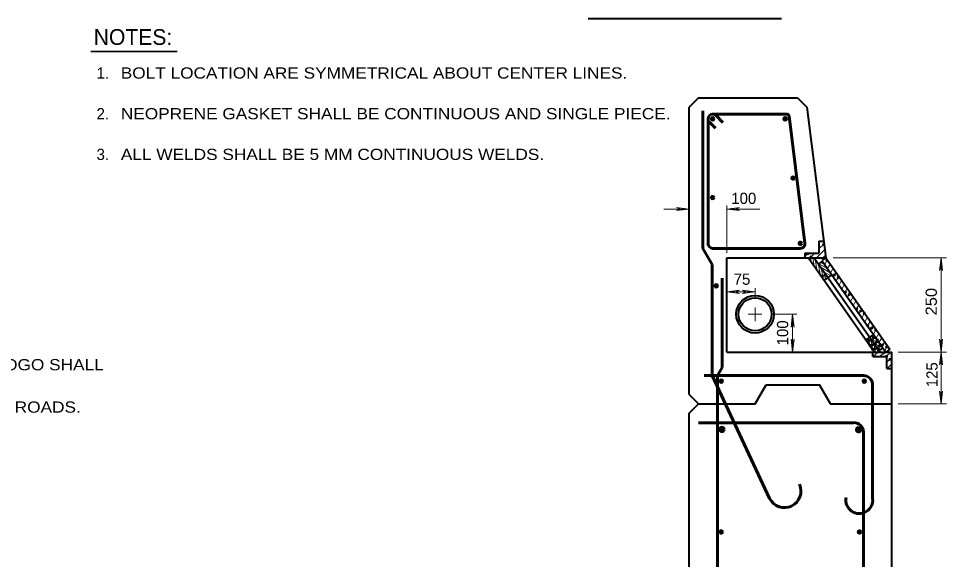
# Model space of a CAD drawing. Extents: x 312583 to 312854, y 144419 to 144597.
# Drawn here: x 312713.6 to 312776.5, y 144507.6 to 144544.3 of the extents above; entities that cross this region are included whole.
import ezdxf
from ezdxf.enums import TextEntityAlignment as Align

# ---------------------------------------------------------------- set-up
doc = ezdxf.new("R2010")
doc.units = 0
doc.header["$LTSCALE"] = 0.3
doc.header["$PDMODE"] = 32
doc.header["$PDSIZE"] = 0.15
doc.layers.add('1', color=7, linetype='Continuous', lineweight=13)

msp = doc.modelspace()

# ---------------------------------------------------------------- linework, layer by layer
at = {"layer": '1', "lineweight": 40}
for p, q in [((312752.2333, 144544.2744), (312765.3439, 144544.2744)), ((312759.7265, 144538.9071), (312759.0902, 144538.2708)), ((312759.7265, 144538.9071), (312766.4348, 144538.9071)), ((312759.0902, 144518.7821), (312759.0902, 144538.2708)), ((312767.8915, 144529.1704), (312767.8915, 144528.3654)), ((312767.8915, 144529.1704), (312768.2135, 144529.1704)), ((312766.9332, 144528.3654), (312767.8915, 144528.3654)), ((312766.9332, 144528.3654), (312766.9332, 144528.0511)), ((312761.6432, 144528.0511), (312768.3515, 144528.0511)), ((312761.6432, 144521.6571), (312761.6432, 144528.0511)), ((312767.1862, 144528.0511), (312771.6558, 144521.6571)), ((312767.5772, 144528.0511), (312772.0468, 144521.6571)), ((312768.1292, 144527.8134), (312767.8685, 144527.6294)), ((312768.3515, 144528.0511), (312768.0908, 144527.8671)), ((312768.0908, 144527.8671), (312772.4378, 144521.6571)), ((312768.3515, 144528.0511), (312772.6985, 144521.8411)), ((312768.7655, 144526.9011), (312768.2442, 144526.5331)), ((312771.6022, 144522.8531), (312771.0808, 144522.4851)), ((312772.2462, 144521.9331), (312771.9855, 144521.7568)), ((312761.6432, 144521.6571), (312772.8288, 144521.6571)), ((312771.5485, 144521.3428), (312771.5485, 144521.6571)), ((312771.5485, 144521.3428), (312772.5068, 144521.3428)), ((312772.6985, 144521.8411), (312772.4378, 144521.6571)), ((312772.5068, 144520.5454), (312772.5068, 144521.3428)), ((312772.8288, 144491.9488), (312772.8288, 144521.6571)), ((312772.5068, 144520.5454), (312772.8288, 144520.5454)), ((312763.5598, 144518.1458), (312764.3035, 144519.4261)), ((312764.3035, 144519.4261), (312767.9375, 144519.4261)), ((312768.6735, 144518.1458), (312767.9375, 144519.4261)), ((312759.0902, 144518.7821), (312759.7265, 144518.1458)), ((312759.0902, 144517.5094), (312759.7265, 144518.1458)), ((312759.7265, 144518.1458), (312763.5598, 144518.1458)), ((312768.6428, 144518.1458), (312772.8288, 144518.1458)), ((312759.0902, 144491.9488), (312759.0902, 144517.5094))]:
    msp.add_line(p, q, dxfattribs=at)
at = {"layer": '1', "lineweight": 35}
msp.add_line((312724.3562, 144542.0512), (312718.5131, 144542.0512), dxfattribs=at)
at = {"layer": '1', "lineweight": 60}
for p, q in [((312760.0178, 144528.6874), (312760.0178, 144538.0101)), ((312760.6848, 144537.7954), (312765.7065, 144537.7954)), ((312760.8918, 144537.7188), (312761.3748, 144537.2358)), ((312765.8675, 144537.6498), (312766.9408, 144529.0478)), ((312760.3705, 144529.0094), (312760.3705, 144537.4734)), ((312760.4472, 144537.2664), (312760.8688, 144536.8371)), ((312760.0178, 144528.6874), (312760.6542, 144527.5834)), ((312760.6848, 144528.6874), (312766.6265, 144528.6874)), ((312760.6542, 144520.0624), (312760.6542, 144527.5834)), ((312761.3288, 144520.6144), (312761.3288, 144526.6634)), ((312761.0068, 144520.0624), (312761.3288, 144520.6144)), ((312760.1022, 144520.0624), (312770.8968, 144520.0624)), ((312760.6542, 144520.0624), (312764.5488, 144511.7288)), ((312761.0068, 144491.9488), (312761.0068, 144520.0624)), ((312771.5332, 144511.7288), (312771.5332, 144519.4261)), ((312759.7265, 144516.8654), (312770.2682, 144516.8654)), ((312770.9122, 144491.9488), (312770.9122, 144516.2291))]:
    msp.add_line(p, q, dxfattribs=at)
at = {"layer": '1'}
for p, q in [((312757.3652, 144531.3554), (312759.0902, 144531.3554)), ((312758.2238, 144531.4628), (312758.4998, 144531.3554)), ((312759.0902, 144531.3554), (312758.2238, 144531.4628)), ((312758.2238, 144531.2481), (312758.4998, 144531.3554)), ((312759.0902, 144531.3554), (312758.2238, 144531.2481)), ((312761.6432, 144528.3961), (312761.6432, 144531.5931)), ((312761.6432, 144531.3554), (312762.5095, 144531.4628)), ((312761.6432, 144531.3554), (312763.8742, 144531.3554)), ((312761.6432, 144531.3554), (312762.5095, 144531.2481)), ((312762.5095, 144531.4628), (312762.2335, 144531.3554)), ((312762.5095, 144531.2481), (312762.2335, 144531.3554)), ((312767.8915, 144529.0861), (312767.9682, 144529.1704)), ((312767.8915, 144528.6568), (312768.2365, 144528.9941)), ((312766.9332, 144528.1278), (312767.1708, 144528.3654)), ((312767.2858, 144528.0511), (312767.6078, 144528.3654)), ((312767.7228, 144528.0511), (312768.2825, 144528.6108)), ((312768.1522, 144528.0511), (312768.3285, 144528.2274)), ((312767.3625, 144527.7981), (312767.3165, 144528.0511)), ((312767.5695, 144527.5068), (312767.4698, 144528.0511)), ((312767.7535, 144527.2308), (312767.6308, 144527.9744)), ((312767.9682, 144526.9394), (312767.8378, 144527.6754)), ((312768.4895, 144527.2998), (312767.8915, 144527.6448)), ((312768.2748, 144527.5988), (312768.0295, 144527.7444)), ((312768.2825, 144527.5911), (312768.4588, 144527.8978)), ((312768.4818, 144527.3151), (312768.6582, 144527.6218)), ((312768.8498, 144528.0511), (312776.5395, 144528.0511)), ((312776.1715, 144528.0511), (312776.0642, 144527.1848)), ((312776.1715, 144528.0511), (312776.2788, 144527.1848)), ((312768.6965, 144527.0084), (312768.0448, 144527.3841)), ((312768.1752, 144526.6404), (312768.0448, 144527.3841)), ((312768.6812, 144526.8398), (312768.2518, 144527.0851)), ((312768.3362, 144526.5944), (312768.2518, 144527.0851)), ((312768.6735, 144527.0391), (312768.8498, 144527.3381)), ((312768.8652, 144526.7554), (312769.0415, 144527.0621)), ((312776.0642, 144527.1848), (312776.1715, 144527.4608)), ((312776.2788, 144527.1848), (312776.1715, 144527.4608)), ((312768.4742, 144526.6941), (312768.4588, 144526.7784)), ((312768.5432, 144526.7401), (312768.4665, 144526.7861)), ((312769.0568, 144526.4794), (312769.2332, 144526.7861)), ((312769.2562, 144526.2034), (312769.4325, 144526.5101)), ((312761.6432, 144525.7358), (312762.5095, 144525.8431)), ((312761.6432, 144525.7358), (312763.5598, 144525.7358)), ((312761.6432, 144525.7358), (312762.5095, 144525.6284)), ((312762.5095, 144525.8431), (312762.2335, 144525.7358)), ((312762.5095, 144525.6284), (312762.2335, 144525.7358)), ((312762.6935, 144525.8431), (312762.9695, 144525.7358)), ((312763.5598, 144525.7358), (312762.6935, 144525.8431)), ((312762.6935, 144525.6284), (312762.9695, 144525.7358)), ((312763.5598, 144525.7358), (312762.6935, 144525.6284)), ((312763.5598, 144525.3141), (312763.5598, 144525.9888)), ((312769.4478, 144525.9274), (312769.6242, 144526.2341)), ((312769.6395, 144525.6514), (312769.8158, 144525.9581)), ((312769.8388, 144525.3754), (312770.0152, 144525.6821)), ((312770.0305, 144525.0918), (312770.2068, 144525.3984)), ((312770.2222, 144524.8158), (312770.3985, 144525.1224)), ((312763.5598, 144524.2178), (312763.5598, 144524.6778)), ((312770.4215, 144524.5398), (312770.5978, 144524.8464)), ((312770.6132, 144524.2638), (312770.7895, 144524.5704)), ((312763.5598, 144524.2178), (312763.0998, 144524.2178)), ((312763.5598, 144524.2178), (312764.0198, 144524.2178)), ((312763.5598, 144524.2178), (312763.5598, 144523.7578)), ((312764.7482, 144524.2178), (312766.3888, 144524.2178)), ((312766.1052, 144524.2178), (312765.9978, 144523.3514)), ((312766.1052, 144521.6571), (312766.1052, 144524.2178)), ((312766.1052, 144524.2178), (312766.2125, 144523.3514)), ((312770.8048, 144523.9878), (312770.9812, 144524.2944)), ((312771.0042, 144523.7118), (312771.1805, 144524.0184)), ((312765.9978, 144523.3514), (312766.1052, 144523.6274)), ((312766.2125, 144523.3514), (312766.1052, 144523.6274)), ((312771.1958, 144523.4358), (312771.3722, 144523.7348)), ((312771.3875, 144523.1521), (312771.5638, 144523.4588)), ((312771.5868, 144522.8761), (312771.7632, 144523.1828)), ((312765.9978, 144522.5234), (312766.1052, 144522.2474)), ((312766.1052, 144521.6571), (312765.9978, 144522.5234)), ((312766.2125, 144522.5234), (312766.1052, 144522.2474)), ((312766.1052, 144521.6571), (312766.2125, 144522.5234)), ((312771.1345, 144522.4084), (312771.1192, 144522.5081)), ((312771.3415, 144522.1171), (312771.2572, 144522.6078)), ((312772.0698, 144522.1861), (312771.4182, 144522.5618)), ((312771.5485, 144521.8181), (312771.4182, 144522.5618)), ((312771.8628, 144522.4774), (312771.4258, 144522.7304)), ((312771.6558, 144522.7764), (312771.5715, 144522.8224)), ((312771.7785, 144522.6001), (312771.9548, 144522.9068)), ((312771.9702, 144522.3241), (312772.1465, 144522.6308)), ((312776.0642, 144522.5234), (312776.1715, 144522.2474)), ((312776.1715, 144521.6571), (312776.0642, 144522.5234)), ((312776.2788, 144522.5234), (312776.1715, 144522.2474)), ((312776.1715, 144521.6571), (312776.2788, 144522.5234)), ((312772.2155, 144521.9178), (312771.6252, 144522.2628)), ((312771.7325, 144521.6571), (312771.6252, 144522.2628)), ((312771.8858, 144521.6571), (312771.8398, 144521.9484)), ((312772.0775, 144521.8258), (312771.8475, 144521.9561)), ((312772.1312, 144522.0941), (312772.2308, 144521.9254)), ((312772.1618, 144522.0481), (312772.3458, 144522.3548)), ((312772.3612, 144521.7721), (312772.5375, 144522.0788)), ((312771.5792, 144521.3428), (312771.9012, 144521.6571)), ((312771.6098, 144521.7261), (312771.6712, 144521.6571)), ((312772.0162, 144521.3428), (312772.3382, 144521.6571)), ((312772.4455, 144521.3428), (312772.7675, 144521.6571)), ((312772.5068, 144520.9671), (312772.8288, 144521.2814)), ((312773.2658, 144521.6571), (312776.5395, 144521.6571)), ((312776.1715, 144521.6571), (312776.0642, 144520.7908)), ((312776.1715, 144521.6571), (312776.2788, 144520.7908)), ((312772.5145, 144520.5454), (312772.8288, 144520.8521)), ((312776.0642, 144520.7908), (312776.1715, 144521.0668)), ((312776.2788, 144520.7908), (312776.1715, 144521.0668)), ((312776.0642, 144519.0121), (312776.1715, 144518.7361)), ((312776.1715, 144518.1458), (312776.0642, 144519.0121)), ((312776.2788, 144519.0121), (312776.1715, 144518.7361)), ((312776.1715, 144518.1458), (312776.2788, 144519.0121)), ((312773.2658, 144518.1458), (312776.5395, 144518.1458))]:
    msp.add_line(p, q, dxfattribs=at)
at = {"layer": '1', "lineweight": 40}
msp.add_lwpolyline([(312766.4348, 144538.9071), (312767.0788, 144538.2708), (312768.3515, 144528.0511)], dxfattribs=at)
at = {"layer": '1'}
msp.add_lwpolyline([(312776.1715, 144518.1458), (312776.1715, 144521.6571), (312776.1715, 144528.0511)], dxfattribs=at)
at = {"layer": '1', "lineweight": 60}
for centre, radius in [((312760.6867, 144537.4734), 0.085), ((312760.6867, 144537.4734), 0.051), ((312760.6867, 144537.4734), 0.0135), ((312765.6036, 144537.4734), 0.085), ((312765.6036, 144537.4734), 0.051), ((312765.6036, 144537.4734), 0.0135), ((312766.1326, 144533.4535), 0.085), ((312766.1326, 144533.4535), 0.051), ((312766.1326, 144533.4535), 0.0135), ((312760.681, 144532.1342), 0.085), ((312760.681, 144532.1342), 0.051), ((312760.681, 144532.1342), 0.0135), ((312766.6265, 144529.0292), 0.085), ((312766.6265, 144529.0292), 0.051), ((312766.6265, 144529.0292), 0.0135), ((312760.9276, 144526.144), 0.085), ((312760.9276, 144526.144), 0.051), ((312760.9276, 144526.144), 0.0135), ((312761.2707, 144519.6791), 0.085), ((312761.2707, 144519.6791), 0.051), ((312761.2707, 144519.6791), 0.0135), ((312770.9639, 144519.6791), 0.085), ((312770.9639, 144519.6791), 0.051), ((312770.9639, 144519.6791), 0.0135), ((312761.3111, 144516.4039), 0.1469), ((312761.3111, 144516.4039), 0.0881), ((312761.3111, 144516.4039), 0.0234), ((312770.5845, 144516.3909), 0.1469), ((312770.5845, 144516.3909), 0.0881), ((312770.5845, 144516.3909), 0.0234), ((312761.2707, 144509.4569), 0.085), ((312761.2707, 144509.4569), 0.051), ((312761.2707, 144509.4569), 0.0135), ((312770.6445, 144509.4569), 0.085), ((312770.6445, 144509.4569), 0.051), ((312770.6445, 144509.4569), 0.0135)]:
    msp.add_circle(centre, radius, dxfattribs=at)
at = {"layer": '1', "lineweight": 40}
for radius in [1.2778, 1.1181]:
    msp.add_circle((312763.5617, 144524.2165), radius, dxfattribs=at)
at = {"layer": '1', "lineweight": 60}
for centre, radius, start, end in [((312760.6867, 144537.4734), 0.3194, 50.2677, 221.03534), ((312765.7065, 144537.6332), 0.1597, 7.12502, 90), ((312760.6867, 144529.0082), 0.3194, 180, 270), ((312766.6237, 144529.0082), 0.3194, 270, 7.12548), ((312770.8956, 144519.4248), 0.6389, 0, 90), ((312770.2701, 144516.2304), 0.6389, 0, 90), ((312765.5525, 144512.2284), 1.122, 206.55046, 23.98617), ((312770.6279, 144511.6157), 0.9134, 169.41749, 6.9908)]:
    msp.add_arc(centre, radius, start, end, dxfattribs=at)
at = {"layer": '1'}
for p in [(312768.2058, 144528.9711), (312767.0022, 144528.3348), (312767.1248, 144528.3194), (312767.3395, 144528.1048), (312768.4435, 144527.8671), (312768.1445, 144526.8168), (312768.2902, 144526.8474), (312768.9342, 144526.8781), (312769.2025, 144526.7248), (312769.6932, 144525.7281), (312769.9538, 144525.5748), (312770.4445, 144524.5858), (312770.7128, 144524.4324), (312770.9735, 144524.2791), (312771.2035, 144523.4434), (312771.4642, 144523.2901), (312771.7325, 144523.1368), (312771.2878, 144522.4238), (312771.4412, 144522.4468), (312771.5178, 144522.5004), (312771.5945, 144522.6384), (312771.8552, 144522.4851), (312771.3415, 144522.1171), (312771.4948, 144522.1478), (312771.5408, 144521.8411), (312771.6405, 144522.1708), (312771.6405, 144522.1631), (312771.6942, 144521.8718), (312771.7018, 144522.2168), (312771.7095, 144522.2091), (312771.7785, 144522.3471), (312771.8475, 144521.8948), (312771.8935, 144521.9331), (312771.9702, 144522.0634), (312772.0468, 144522.1938), (312772.2232, 144522.1478), (312772.4915, 144521.9944), (312771.6175, 144521.3734), (312772.2692, 144521.5958), (312772.4838, 144521.3734), (312772.6985, 144521.1588)]:
    msp.add_point(p, dxfattribs=at)

# ---------------------------------------------------------------- texts
msp.add_text('NOTES:', height=1.07, dxfattribs=at).set_placement((312721.3684, 144542.4879), align=Align.CENTER)
for s, p in [('1. ', (312718.8976, 144540.2025)), ('2.', (312718.8976, 144537.4425)), ('3.', (312718.8976, 144534.6825)), ('100', (312761.9441, 144531.7024)), ('75', (312762.1086, 144526.2169))]:
    msp.add_text(s, height=0.76, dxfattribs=at).set_placement(p)
at = {"layer": '1', "width": 1.15}
for s, p in [('BOLT LOCATION ARE SYMMETRICAL ABOUT CENTER LINES.', (312720.5382, 144540.2025)), ('NEOPRENE GASKET SHALL BE CONTINUOUS AND SINGLE PIECE.', (312720.5459, 144537.4425)), ('ALL WELDS SHALL BE 5 MM CONTINUOUS WELDS.', (312720.5459, 144534.6825)), ('JUNCTION BOX COVER WITHOUT D.O.T. LOGO SHALL', (312688.9281, 144520.4183)), ('INTERSECTIONS AND BRIDGES ON LOCAL ROADS.', (312688.9281, 144517.5433))]:
    msp.add_text(s, height=0.76, dxfattribs=at).set_placement(p)
at = {"layer": '1', "width": 1.1}
msp.add_text('250', height=0.76, rotation=90, dxfattribs=at).set_placement((312775.8865, 144524.1406))
at = {"layer": '1'}
for s, p in [('100', (312765.8047, 144522.1103)), ('125', (312775.9421, 144519.2678))]:
    msp.add_text(s, height=0.76, rotation=90, dxfattribs=at).set_placement(p)

doc.saveas('drawing.dxf')
